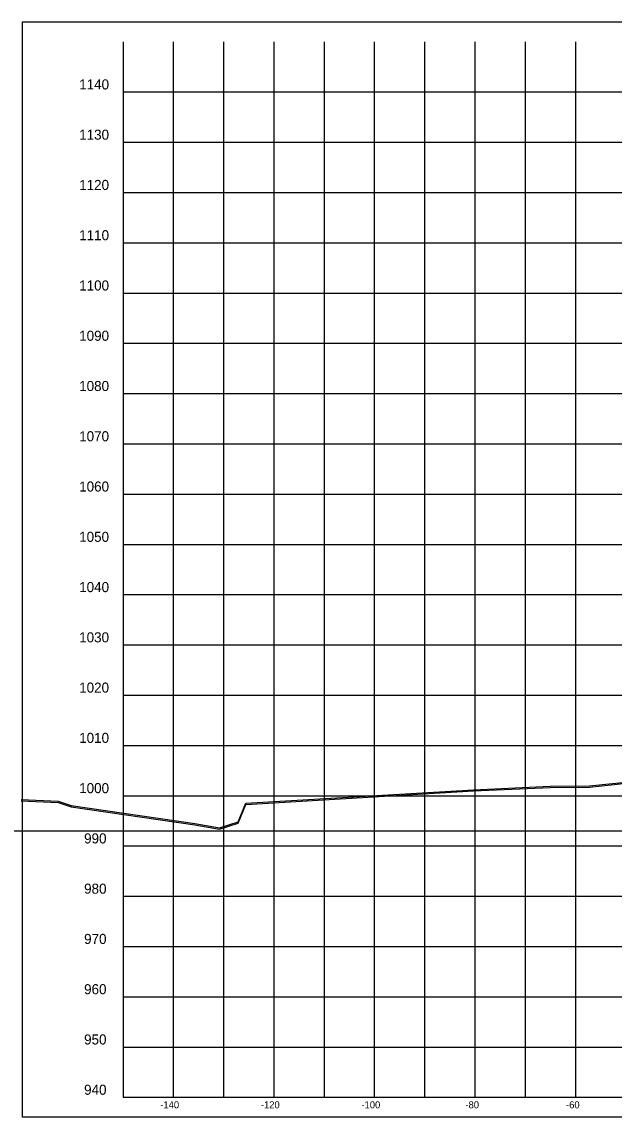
# Model space of a CAD drawing. Extents: x 1131015 to 1136271, y 133453 to 174329.
# Drawn here: x 1132170.3 to 1132288.1, y 159610.7 to 159828.6 of the extents above; entities that cross this region are included whole.
import ezdxf

# ---------------------------------------------------------------- set-up
doc = ezdxf.new("R2010")
doc.units = 0
for name, color, linetype in [('DESIGN - SHEET - Corner Text', 7, 'Continuous'), ('DESIGN - SHEET - Light Grid', 7, 'Continuous'), ('DESIGN - SHEET - Linework', 7, 'Continuous'), ('DESIGN - SHEET - Plot Shape', 7, 'Continuous'), ('SURVEY - GROUND - Bottom of Topsoil Layer', 7, 'Continuous'), ('SURVEY - GROUND - Top of Ground', 7, 'Continuous')]:
    doc.layers.add(name, color=color, linetype=linetype)

msp = doc.modelspace()

# ---------------------------------------------------------------- linework, layer by layer
at = {"layer": 'DESIGN - SHEET - Light Grid'}
msp.add_line((1132040.46, 159667.66), (1132340.46, 159667.66), dxfattribs=at)
at = {"layer": 'DESIGN - SHEET - Linework'}
for p, q in [((1132200.46, 159614.66), (1132200.46, 159824.66)), ((1132210.46, 159614.66), (1132210.46, 159824.66)), ((1132220.46, 159614.66), (1132220.46, 159824.66)), ((1132230.46, 159614.66), (1132230.46, 159824.66)), ((1132240.46, 159614.66), (1132240.46, 159824.66)), ((1132250.46, 159614.66), (1132250.46, 159824.66)), ((1132260.46, 159614.66), (1132260.46, 159824.66)), ((1132270.46, 159614.66), (1132270.46, 159824.66)), ((1132280.46, 159614.66), (1132280.46, 159824.66)), ((1132190.46, 159814.66), (1132490.46, 159814.66)), ((1132190.46, 159804.66), (1132490.46, 159804.66)), ((1132190.46, 159794.66), (1132490.46, 159794.66)), ((1132190.46, 159784.66), (1132490.46, 159784.66)), ((1132190.46, 159774.66), (1132490.46, 159774.66)), ((1132190.46, 159764.66), (1132490.46, 159764.66)), ((1132190.46, 159754.66), (1132490.46, 159754.66)), ((1132190.46, 159744.66), (1132490.46, 159744.66)), ((1132190.46, 159734.66), (1132490.46, 159734.66)), ((1132190.46, 159724.66), (1132490.46, 159724.66)), ((1132190.46, 159714.66), (1132490.46, 159714.66)), ((1132190.46, 159704.66), (1132490.46, 159704.66)), ((1132190.46, 159694.66), (1132490.46, 159694.66)), ((1132190.46, 159684.66), (1132490.46, 159684.66)), ((1132190.46, 159674.66), (1132490.46, 159674.66)), ((1132190.46, 159664.66), (1132490.46, 159664.66)), ((1132190.46, 159654.66), (1132490.46, 159654.66)), ((1132190.46, 159644.66), (1132490.46, 159644.66)), ((1132190.46, 159634.66), (1132490.46, 159634.66)), ((1132190.46, 159624.66), (1132490.46, 159624.66))]:
    msp.add_line(p, q, dxfattribs=at)
msp.add_lwpolyline([(1132190.46, 159824.66), (1132190.46, 159614.66), (1132490.46, 159614.66), (1132490.46, 159824.66)], dxfattribs=at)
at = {"layer": 'DESIGN - SHEET - Plot Shape'}
msp.add_lwpolyline([(1132170.46, 159828.6), (1132510.46, 159828.6), (1132510.46, 159610.72), (1132170.46, 159610.72)], close=True, dxfattribs=at)
at = {"layer": 'SURVEY - GROUND - Bottom of Topsoil Layer'}
for p, q in [((1132283.21, 159676.34), (1132311.15, 159679.35)), ((1132214.85, 159672.9), (1132260.12, 159675.6)), ((1132260.12, 159675.6), (1132275.34, 159676.29)), ((1132275.34, 159676.29), (1132283.21, 159676.34)), ((1132170.18, 159673.65), (1132177.51, 159673.29)), ((1132177.51, 159673.29), (1132180.08, 159672.47)), ((1132180.08, 159672.47), (1132204.68, 159668.89)), ((1132213.3, 159669.18), (1132214.85, 159672.9)), ((1132209.6, 159667.99), (1132213.3, 159669.18)), ((1132204.68, 159668.89), (1132209.6, 159667.99))]:
    msp.add_line(p, q, dxfattribs=at)
at = {"layer": 'SURVEY - GROUND - Top of Ground'}
for p, q in [((1132283.21, 159676.59), (1132311.15, 159679.6)), ((1132214.85, 159673.15), (1132260.12, 159675.85)), ((1132260.12, 159675.85), (1132275.34, 159676.54)), ((1132275.34, 159676.54), (1132283.21, 159676.59)), ((1132170.18, 159673.9), (1132177.51, 159673.54)), ((1132177.51, 159673.54), (1132180.08, 159672.72)), ((1132180.08, 159672.72), (1132204.68, 159669.14)), ((1132213.3, 159669.43), (1132214.85, 159673.15)), ((1132204.68, 159669.14), (1132209.6, 159668.24)), ((1132209.6, 159668.24), (1132213.3, 159669.43))]:
    msp.add_line(p, q, dxfattribs=at)

# ---------------------------------------------------------------- texts
at = {"layer": 'DESIGN - SHEET - Corner Text'}
for s, height, p in [('1140', 2, (1132181.7, 159815.16)), ('1130', 2, (1132181.7, 159805.16)), ('1120', 2, (1132181.7, 159795.16)), ('1110', 2, (1132181.7, 159785.16)), ('1100', 2, (1132181.7, 159775.16)), ('1090', 2, (1132181.7, 159765.16)), ('1080', 2, (1132181.7, 159755.16)), ('1070', 2, (1132181.7, 159745.16)), ('1060', 2, (1132181.7, 159735.16)), ('1050', 2, (1132181.7, 159725.16)), ('1040', 2, (1132181.7, 159715.16)), ('1030', 2, (1132181.7, 159705.16)), ('1020', 2, (1132181.7, 159695.16)), ('1010', 2, (1132181.7, 159685.16)), ('1000', 2, (1132181.7, 159675.16)), ('990', 2, (1132182.68, 159665.16)), ('980', 2, (1132182.68, 159655.16)), ('970', 2, (1132182.68, 159645.16)), ('960', 2, (1132182.68, 159635.16)), ('950', 2, (1132182.68, 159625.16)), ('940', 2, (1132182.68, 159615.16)), ('-140', 1.4, (1132197.83, 159612.46)), ('-120', 1.4, (1132217.83, 159612.46)), ('-100', 1.4, (1132237.83, 159612.46)), ('-80', 1.4, (1132258.51, 159612.46)), ('-60', 1.4, (1132278.51, 159612.46))]:
    msp.add_text(s, height=height, dxfattribs=at).set_placement(p)

doc.saveas('drawing.dxf')
